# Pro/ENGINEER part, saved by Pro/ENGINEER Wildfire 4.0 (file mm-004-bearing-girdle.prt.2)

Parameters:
  METRIC = "NO"

Other parameters: PITCH, DRILL_POINT_ANGLE, DRILL_DEPTH, DRILL_DIAMETER, THREAD_DIAMETER, THREADS_PER_INCH, THREAD_DEPTH, THREAD_LENGTH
